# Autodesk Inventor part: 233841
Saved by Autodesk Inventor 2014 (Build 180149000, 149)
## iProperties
Shininess: 64.0
Length Units: 11272
Angle Units: 11279
Time Units: 11290
Mass Units: 11286
Length Display Precision: 3
Angle Display Precision: 2
Company: Autodesk, Inc.
Created: 2001-12
Part Number: 233841
Material: Stainless Steel, 440C
Description: FITTING; ST-G24-J16-(SS)
Document SubType Name: Modeling
Designer: Autodesk, Inc.
Density: 7.75 g/cm^3
Mass: 356.085 g
Surface Area: 127.469 cm^2
Volume: 45.9464 cm^3
Appearance: Stainless Steel
Density: 7.75
Volumn: 1.1899929784618444
Area: 7.049002142317107
PropertySet Name: Model Information
Control State: 0
Master: False
Checked Out: False
Last Check In By: JT
Last Check In Date: 2003-06-20
Title: FITTING; ST-G24-J16-(SS)
Author: Autodesk, Inc.
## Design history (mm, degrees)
sketch "Sketch1"
  geometry: L1 (26.988, -15.581)-(0, -31.162); L2 (0, -31.162)-(-26.988, -15.581); L3 (-26.988, -15.581)-(-26.988, 15.581); L4 (-26.988, 15.581)-(0, 31.162); L5 (0, 31.162)-(26.987, 15.581); L6 (26.987, 15.581)-(26.988, -15.581); C1 r 26.988 at (0, 0); 2 further points
  constraints: 12 end point, 2 coincident, 1 centre point, 1 tangent, 1 vertical, 11 other
  dimensions: "Hex_Flats" = 53.975 diameter of C1
extrude "Extrusion1" new body sketch "Sketch1" taper "d2" = 0 deg; distance "Hex_Thickness" = 17.272 (= Total_Length - Thread_Length)
sketch "Sketch2"
  geometry: L1 (0, 31.162)-(26.987, 15.581) reference; L2 (-26.988, -15.581)-(-26.988, 15.581) reference; L3 (-26.988, 15.581)-(26.988, -15.581); L4 (0, -31.162)-(0, 31.162); C1 r 23.812 at (0, 0)
  constraints: 4 end point, 2 parallel, 1 centre point, 1 midpoint
  dimensions: "Thread_Size" = 47.625 diameter of C1
extrude "Extrusion2" join sketch "Sketch2" taper "d5" = 0 deg; distance "Thread_Length" = 14.986
sketch "Sketch3"
  geometry: L1 (31.162, 0)-(31.162, 17.272) reference; L2 (-31.162, 0)-(-31.162, 17.272) reference; L3 (31.162, 17.272)-(-31.162, 17.272); L4 (-31.162, 0)-(31.162, 0); L5 (-31.162, 16.153)-(-26.988, 17.272); L6 (-31.162, 1.119)-(-26.988, 0); L7 (0, 17.272)-(0, 0)
  constraints: 10 end point, 4 point on line, 2 midpoint, 1 equal length, 1 parallel, 1 perpendicular, 1 vertical alignment
  dimensions: "d15" = 15 deg angle of L4 L6; "d16" = 53.975 diameter of L6.end L7 (= Hex_Flats)
revolve "Revolution1" sketch "Sketch3" stored, may be unused: angle "d8" = 90 deg
chamfer "Chamfer1" distance "d9" = 0.79375; stored, may be unused: second distance "d10" = 0.79375, angle "d28" = 45 deg
sketch "Sketch4" dims "Oring_Thickness" = 1.778
  geometry: L1 (-23.812, 17.272)-(-23.812, 31.464) reference; L2 (0, 14.434)-(0, 34.303) reference; 1 further point
  constraints: 1 point on line, 1 vertical alignment, 2 other
revolve "Revolution2" sketch "Sketch4" stored, may be unused: angle "d12" = 90 deg
thread "Thread1" dims "d13" = 25.4, "d14" = 0
sketch "Sketch5"
  geometry: L1 (0, 0)-(0, 40.8); L2 (0, 40.8)-(9.131, 38.178); L3 (9.131, 38.178)-(9.131, 26.566); L4 (9.131, 26.566)-(16.669, 23.52); L5 (16.669, 23.52)-(16.669, 3.81); L6 (16.669, 3.81)-(17.554, 0.508); L7 (17.554, 0.508)-(24.257, 0.508); L8 (24.257, 0.508)-(24.257, 0); L9 (24.257, 0)-(0, 0)
  constraints: 18 end point, 3 perpendicular, 2 parallel, 1 vertical
  dimensions: "d17" = 33.3375 diameter of L5 L1; "d18" = 0.508 distance of L7.end L8.end; "d19" = 48.514 diameter of L8.end L1; "d20" = 15 deg angle of L5 L6; "d21" = 3.302 vertical distance of L5.end L6.end; "d22" = 23.0124 distance from line of L7 L4.end; "d23" = 68 deg angle of L5 L4; "d24" = 18.2626 diameter of L3 L1
revolve "Revolution3" sketch "Sketch5" stored, may be unused: angle "d25" = 90 deg
thread "Thread2" dims "d26" = 25.4, "d27" = 0
body "Solid1"
other parameters: "Total_Length" = 32.258 [user parameter; used in 1 equation term]
